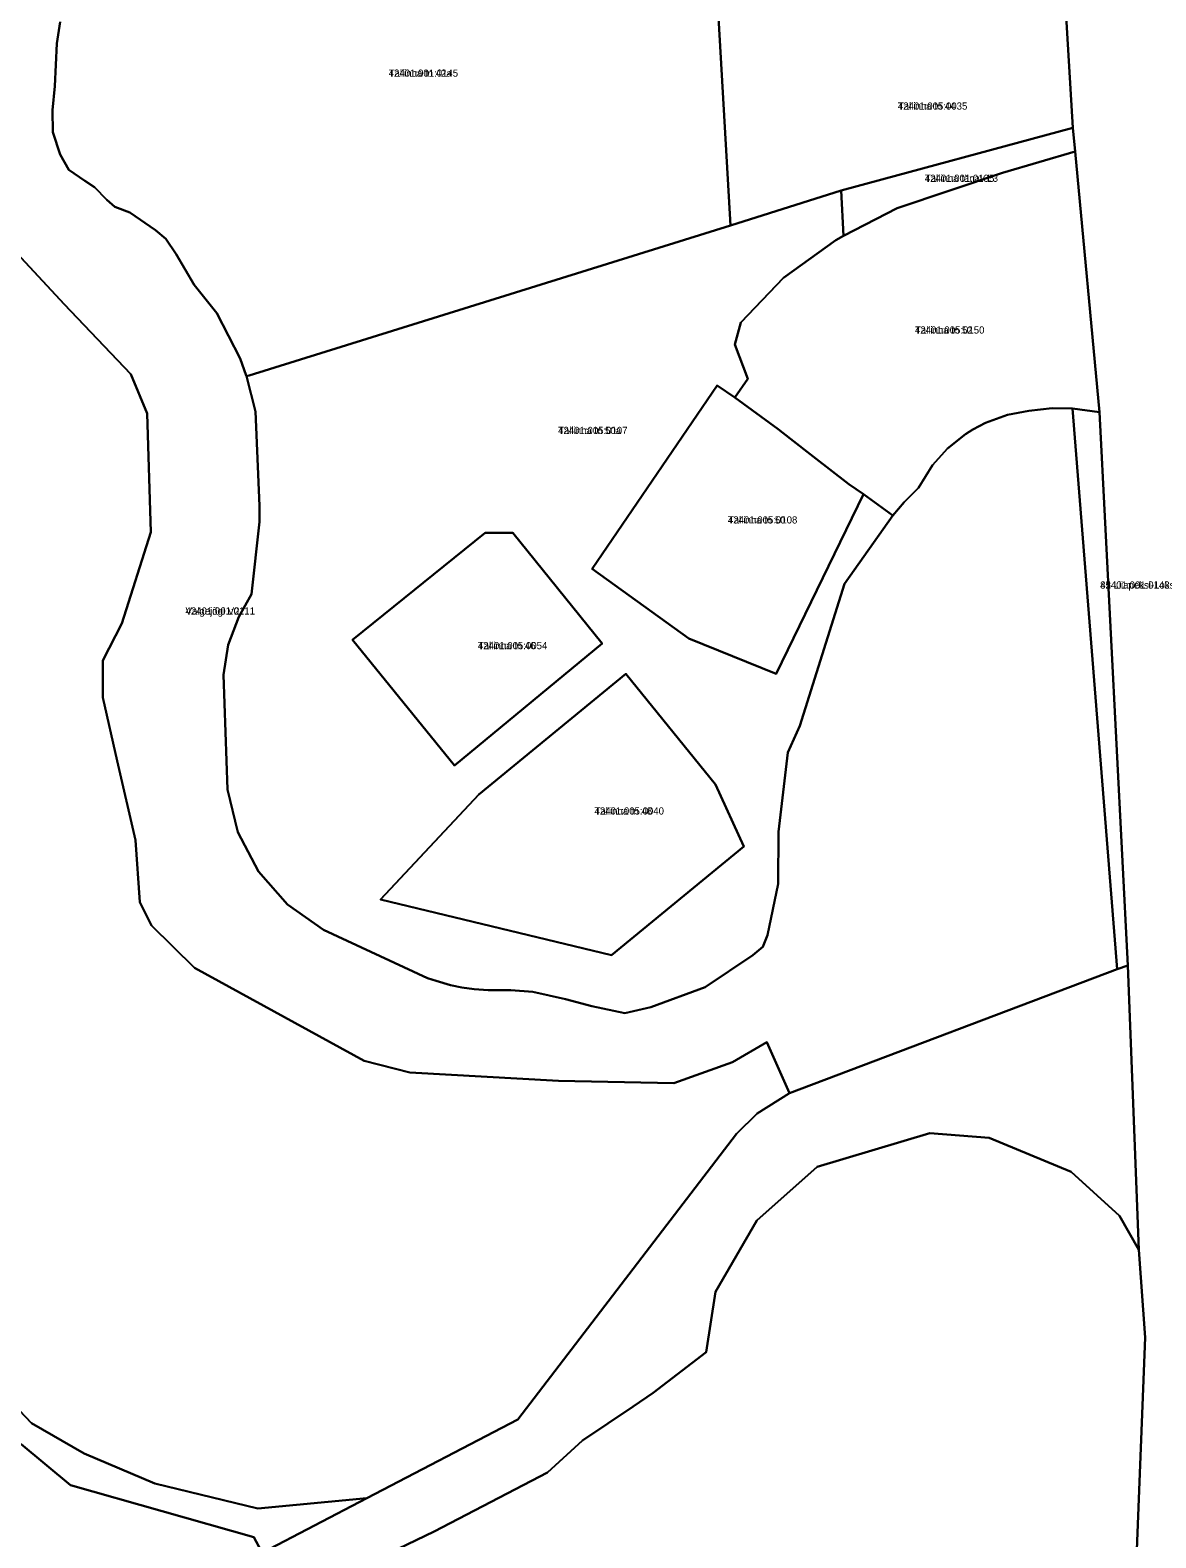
# Model space of a CAD drawing. Extents: x 595979 to 597983, y 6604231 to 6607350.
# Drawn here: x 597254.4 to 597489.5, y 6605469.2 to 6605784.1 of the extents above; entities that cross this region are included whole.
import ezdxf

# ---------------------------------------------------------------- set-up
doc = ezdxf.new("R2010")
doc.units = 0
for name, color, linetype in [('L_AADRESS', 7, 'Continuous'), ('PIIR', 7, 'Continuous'), ('TUNNUS', 7, 'Continuous')]:
    doc.layers.add(name, color=color, linetype=linetype)

msp = doc.modelspace()

# ---------------------------------------------------------------- linework, layer by layer
at = {"layer": 'PIIR'}
for points in [[(597483.61, 6605418.8), (597487.25, 6605511.01), (597485.88, 6605529.34), (597483.58, 6605588.75), (597477.72, 6605704.26), (597472.63, 6605758.73), (597472.15, 6605763.69), (597470.46, 6605791.65), (597465.11, 6605849.2), (597488.98, 6605855.16), (597490.09, 6605844.44), (597491.22, 6605839.74), (597491.66, 6605823.87), (597496.25, 6605783.15), (597494.72, 6605768.17), (597499.41, 6605731.99), (597499.16, 6605692.44), (597499.62, 6605675), (597504.66, 6605540.85), (597499.14, 6605531.46), (597498.96, 6605521.02), (597498.55, 6605497.68), (597495.69, 6605445.75)], [(597398.02, 6605789.18), (597400.63, 6605743.31), (597300.09, 6605711.95), (597299.55, 6605711.79), (597299.52, 6605711.97), (597298.23, 6605715.47), (597293.4, 6605724.95), (597288.61, 6605730.9), (597284.86, 6605737.28), (597282.72, 6605740.49), (597280.59, 6605742.28), (597275.22, 6605745.99), (597272.07, 6605747.19), (597270.4, 6605748.63), (597267.82, 6605751.3), (597265.8, 6605752.58), (597262.49, 6605754.93), (597260.64, 6605758.12), (597259.11, 6605762.76), (597259.06, 6605767.35), (597259.56, 6605772.41), (597259.93, 6605781.32), (597260.68, 6605785.82)], [(597260.68, 6605785.82), (597259.93, 6605781.32), (597259.56, 6605772.41), (597259.06, 6605767.35), (597259.11, 6605762.76), (597260.64, 6605758.12), (597262.49, 6605754.93), (597265.8, 6605752.58), (597267.82, 6605751.3), (597270.4, 6605748.63), (597272.07, 6605747.19), (597275.22, 6605745.99), (597280.59, 6605742.28), (597282.72, 6605740.49), (597284.86, 6605737.28), (597288.61, 6605730.9), (597293.4, 6605724.95), (597298.23, 6605715.47), (597299.52, 6605711.97), (597299.55, 6605711.79), (597301.46, 6605704.43), (597302.29, 6605684.76), (597302.27, 6605681.4), (597300.63, 6605666.26), (597297.99, 6605661.57), (597295.75, 6605655.69), (597294.75, 6605649.4), (597295.58, 6605625.5), (597297.77, 6605616.57), (597302.05, 6605608.37), (597308.12, 6605601.43), (597315.64, 6605596.15), (597337.36, 6605586.11), (597339.2, 6605585.51), (597342.13, 6605584.63), (597344.5, 6605584.16), (597347.07, 6605583.77), (597350.03, 6605583.58), (597354.76, 6605583.59), (597359.37, 6605583.23), (597366.19, 6605581.71), (597371.67, 6605580.23), (597378.56, 6605578.78), (597384.03, 6605579.99), (597395.32, 6605584.23), (597405.33, 6605590.91), (597407.41, 6605592.59), (597408.39, 6605595.08), (597410.56, 6605605.75), (597410.67, 6605616.64), (597412.64, 6605633.23), (597415.14, 6605638.81), (597424.46, 6605668.46), (597434.51, 6605682.69), (597436.9, 6605685.52), (597439.89, 6605688.49), (597442.82, 6605693.21), (597445.95, 6605696.69), (597449.7, 6605699.71), (597451.22, 6605700.67), (597453.9, 6605702.07), (597458.45, 6605703.71), (597462.92, 6605704.55), (597467.81, 6605705.1), (597472.08, 6605705.05), (597481.4, 6605587.93), (597412.95, 6605562.09), (597408.2, 6605572.72), (597401.04, 6605568.5), (597388.79, 6605564.13), (597364.7, 6605564.61), (597333.66, 6605566.35), (597324.15, 6605568.82), (597288.7, 6605588.25), (597279.74, 6605597.08), (597277.29, 6605601.98), (597276.35, 6605614.92), (597272.53, 6605631.46), (597269.55, 6605644.71), (597269.55, 6605652.4), (597273.55, 6605660.15), (597279.55, 6605679.2), (597278.8, 6605703.98), (597275.42, 6605712.25), (597261.46, 6605726.85), (597242.56, 6605747.16)], [(597242.56, 6605747.16), (597261.46, 6605726.85), (597275.42, 6605712.25), (597278.8, 6605703.98), (597279.55, 6605679.2), (597273.55, 6605660.15), (597269.55, 6605652.4), (597269.55, 6605644.71), (597272.53, 6605631.46), (597276.35, 6605614.92), (597277.29, 6605601.98), (597279.74, 6605597.08), (597288.7, 6605588.25), (597324.15, 6605568.82), (597333.66, 6605566.35), (597364.7, 6605564.61), (597388.79, 6605564.13), (597401.04, 6605568.5), (597408.2, 6605572.72), (597412.95, 6605562.09), (597406.22, 6605557.79), (597401.87, 6605553.53), (597356.25, 6605493.89), (597324.71, 6605477.46), (597301.96, 6605475.33), (597280.39, 6605480.52), (597265.65, 6605486.81), (597254.66, 6605493.15), (597249.71, 6605498.34)], [(597302.84, 6605466.06), (597324.71, 6605477.46), (597356.25, 6605493.89), (597401.87, 6605553.53), (597406.22, 6605557.79), (597412.95, 6605562.09), (597481.4, 6605587.93), (597483.58, 6605588.75), (597485.88, 6605529.34), (597481.89, 6605536.47), (597471.77, 6605545.62), (597454.62, 6605552.7), (597442.25, 6605553.7), (597418.75, 6605546.7), (597406.16, 6605535.45), (597397.47, 6605520.58), (597395.52, 6605507.95), (597384.47, 6605499.49), (597380.32, 6605496.6), (597369.74, 6605489.54), (597362.4, 6605482.81), (597338.73, 6605470.54), (597316.36, 6605459.7)], [(597316.36, 6605459.7), (597338.73, 6605470.54), (597362.4, 6605482.81), (597369.74, 6605489.54), (597380.32, 6605496.6), (597384.47, 6605499.49), (597395.52, 6605507.95), (597397.47, 6605520.58), (597406.16, 6605535.45), (597418.75, 6605546.7), (597442.25, 6605553.7), (597454.62, 6605552.7), (597471.77, 6605545.62), (597481.89, 6605536.47), (597485.88, 6605529.34), (597487.25, 6605511.01), (597483.61, 6605418.8)], [(597249.71, 6605498.34), (597254.66, 6605493.15), (597265.65, 6605486.81), (597280.39, 6605480.52), (597301.96, 6605475.33), (597324.71, 6605477.46), (597302.84, 6605466.06), (597301.12, 6605469.32), (597262.8, 6605480.17), (597252.5, 6605488.75)]]:
    msp.add_lwpolyline(points, dxfattribs=at)
for points in [[(597422.51, 6605790), (597426.92, 6605790.23), (597427.02, 6605788.53), (597470.46, 6605791.65), (597472.15, 6605763.69), (597423.76, 6605750.56), (597400.63, 6605743.31), (597398.02, 6605789.18)], [(597435.43, 6605746.87), (597424.25, 6605741.11), (597423.76, 6605750.56), (597472.15, 6605763.69), (597472.63, 6605758.73), (597457.45, 6605754.26)], [(597422.62, 6605740.22), (597424.25, 6605741.11), (597435.43, 6605746.87), (597457.45, 6605754.26), (597472.63, 6605758.73), (597477.72, 6605704.26), (597472.08, 6605705.05), (597467.81, 6605705.1), (597462.92, 6605704.55), (597458.45, 6605703.71), (597453.9, 6605702.07), (597451.22, 6605700.67), (597449.7, 6605699.71), (597445.95, 6605696.69), (597442.82, 6605693.21), (597439.89, 6605688.49), (597436.9, 6605685.52), (597434.51, 6605682.69), (597428.41, 6605687.16), (597425.37, 6605689.24), (597417.87, 6605695.02), (597413.19, 6605698.69), (597410.59, 6605700.75), (597401.56, 6605707.37), (597404.23, 6605711.25), (597401.52, 6605718.44), (597402.77, 6605722.99), (597411.73, 6605732.32)], [(597300.09, 6605711.95), (597400.63, 6605743.31), (597423.76, 6605750.56), (597424.25, 6605741.11), (597422.62, 6605740.22), (597411.73, 6605732.32), (597402.77, 6605722.99), (597401.52, 6605718.44), (597404.23, 6605711.25), (597401.56, 6605707.37), (597397.85, 6605709.88), (597371.78, 6605671.58), (597391.91, 6605656.99), (597410.19, 6605649.67), (597428.41, 6605687.16), (597434.51, 6605682.69), (597424.46, 6605668.46), (597415.14, 6605638.81), (597412.64, 6605633.23), (597410.67, 6605616.64), (597410.56, 6605605.75), (597408.39, 6605595.08), (597407.41, 6605592.59), (597405.33, 6605590.91), (597395.32, 6605584.23), (597384.03, 6605579.99), (597378.56, 6605578.78), (597371.67, 6605580.23), (597366.19, 6605581.71), (597359.37, 6605583.23), (597354.76, 6605583.59), (597350.03, 6605583.58), (597347.07, 6605583.77), (597344.5, 6605584.16), (597342.13, 6605584.63), (597339.2, 6605585.51), (597337.36, 6605586.11), (597315.64, 6605596.15), (597308.12, 6605601.43), (597302.05, 6605608.37), (597297.77, 6605616.57), (597295.58, 6605625.5), (597294.75, 6605649.4), (597295.75, 6605655.69), (597297.99, 6605661.57), (597300.63, 6605666.26), (597302.27, 6605681.4), (597302.29, 6605684.76), (597301.46, 6605704.43), (597299.55, 6605711.79)], [(597397.85, 6605709.88), (597401.56, 6605707.37), (597410.59, 6605700.75), (597413.19, 6605698.69), (597417.87, 6605695.02), (597425.37, 6605689.24), (597428.41, 6605687.16), (597410.19, 6605649.67), (597391.91, 6605656.99), (597371.78, 6605671.58)], [(597481.4, 6605587.93), (597472.08, 6605705.05), (597477.72, 6605704.26), (597483.58, 6605588.75)], [(597349.43, 6605679.07), (597355.2, 6605679.08), (597373.84, 6605655.95), (597342.97, 6605630.5), (597321.72, 6605656.77)], [(597321.72, 6605656.77), (597342.97, 6605630.5), (597373.84, 6605655.95), (597355.2, 6605679.08), (597349.43, 6605679.07)], [(597397.48, 6605626.53), (597403.41, 6605613.56), (597375.76, 6605590.89), (597327.56, 6605602.51), (597348.05, 6605624.45), (597378.76, 6605649.61)], [(597348.05, 6605624.45), (597327.56, 6605602.51), (597375.76, 6605590.89), (597403.41, 6605613.56), (597397.48, 6605626.53), (597378.76, 6605649.61)], [(597232.23, 6605450.89), (597231.64, 6605450.82), (597201.09, 6605497.22), (597248.64, 6605490.2), (597252.5, 6605488.75), (597262.8, 6605480.17), (597301.12, 6605469.32), (597304.83, 6605462.35), (597246.04, 6605430.3)]]:
    msp.add_lwpolyline(points, close=True, dxfattribs=at)

# ---------------------------------------------------------------- texts
at = {"layer": 'L_AADRESS'}
for s, p in [('Tallinna tn 42a', (597329.25, 6605774.36)), ('Tallinna tn 44', (597435.59, 6605767.48)), ('Tallinna tänav L3', (597441.22, 6605752.4)), ('Tallinna tn 52', (597439.16, 6605720.71)), ('Tallinna tn 50a', (597364.63, 6605699.73)), ('Tallinna tn 50', (597400.09, 6605681.04)), ('85 Liiapeksi-Loksa tee L1', (597477.83, 6605667.44)), ('Valgejõgi V2', (597286.83, 6605662.01)), ('Tallinna tn 46', (597347.88, 6605654.79)), ('Tallinna tn 48', (597372.24, 6605620.25))]:
    msp.add_text(s, height=1.5, dxfattribs=at).set_placement(p)
at = {"layer": 'TUNNUS'}
for s, p in [('42401:001:0145', (597329.25, 6605774.36)), ('42401:005:0035', (597435.59, 6605767.48)), ('42401:001:0135', (597441.22, 6605752.4)), ('42401:005:0150', (597439.16, 6605720.71)), ('42401:005:0107', (597364.63, 6605699.73)), ('42401:005:0108', (597400.09, 6605681.04)), ('42401:001:0143', (597477.83, 6605667.44)), ('42401:001:0111', (597286.83, 6605662.01)), ('42401:005:0054', (597347.88, 6605654.79)), ('42401:005:0040', (597372.24, 6605620.25))]:
    msp.add_text(s, height=1.5, dxfattribs=at).set_placement(p)

doc.saveas('drawing.dxf')
